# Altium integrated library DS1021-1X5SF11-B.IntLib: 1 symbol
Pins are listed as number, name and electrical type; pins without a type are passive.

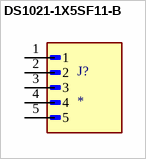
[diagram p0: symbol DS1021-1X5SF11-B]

## DS1021-1X5SF11-B
designator J?
5 position 2.54mm single row vertical pin header through hole; MF: Connfly; MP: DS1021-1X5SF11-B
footprint CONNFLY_DS1021-1X5SF11-B
pins: 1, 2, 3, 4, 5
